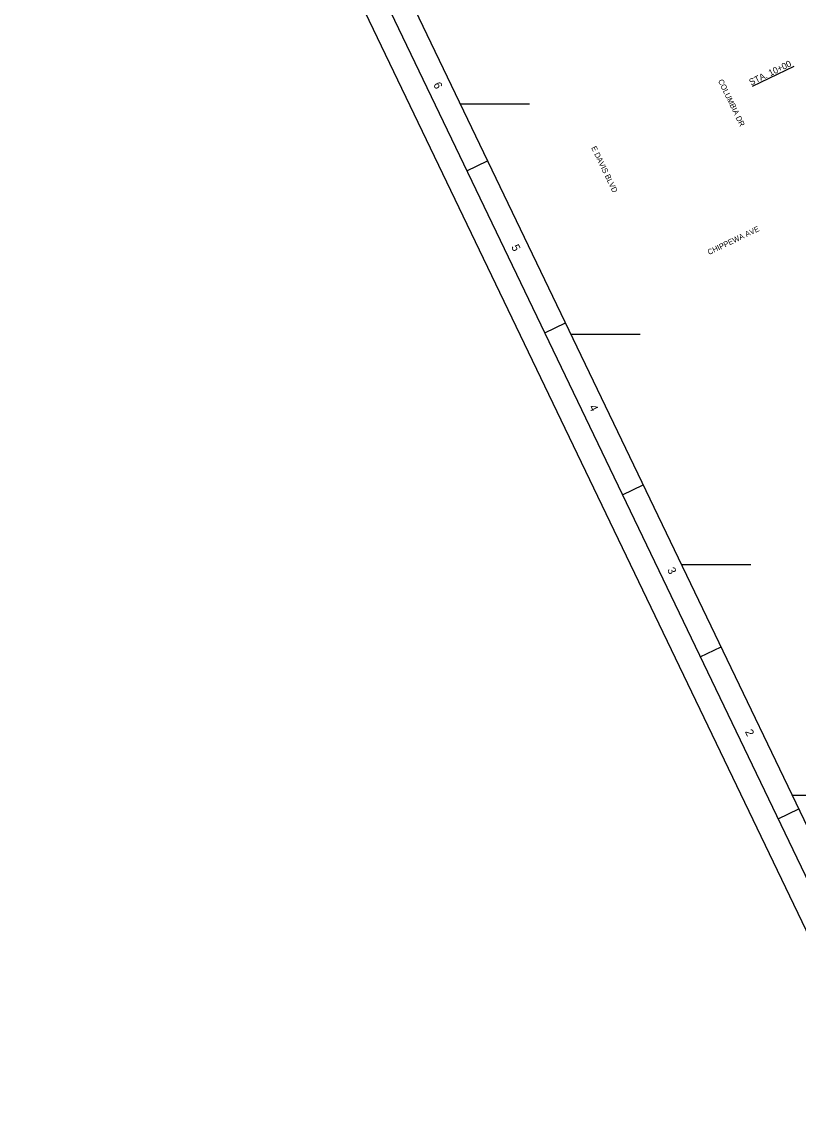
# Model space of a CAD drawing. Extents: x 508947 to 513916, y 1303283 to 1308721.
# Drawn here: x 508947 to 510632, y 1303283 to 1305678 of the extents above; entities that cross this region are included whole.
import ezdxf

# ---------------------------------------------------------------- set-up
doc = ezdxf.new("R2010")
doc.units = 0
for name, color, linetype in [('G-ANNO-NPLT', 7, 'Continuous'), ('G-ANNO-TTLB', 7, 'Continuous'), ('V-ALGN-TEXT', 7, 'Continuous'), ('V-ROAD-IDEN', 7, 'Continuous'), ('V-TOPO-COOR-STAT', 7, 'Continuous')]:
    doc.layers.add(name, color=color, linetype=linetype)

msp = doc.modelspace()

# ---------------------------------------------------------------- linework, layer by layer
at = {"layer": 'G-ANNO-NPLT'}
msp.add_lwpolyline([(512011.7, 1308720.8), (513916.1, 1304754.3), (510851.1, 1303282.7), (508946.7, 1307249.2)], close=True, dxfattribs=at)
at = {"layer": 'G-ANNO-TTLB'}
for p, q in [((509911.5, 1305355.2), (509956.6, 1305376.9)), ((510080.3, 1305003.7), (510125.4, 1305025.3)), ((510249.1, 1304652.1), (510294.2, 1304673.7)), ((510417.9, 1304300.5), (510463, 1304322.2)), ((510586.7, 1303948.9), (510631.8, 1303970.6))]:
    msp.add_line(p, q, dxfattribs=at)
for points in [[(509013.4, 1307225.8), (510874.5, 1303349.5), (513849.4, 1304777.8), (511988.3, 1308654.1)], [(513782.7, 1304801.2), (511997.3, 1308519.8), (509112.6, 1307134.8), (510898, 1303416.2)]]:
    msp.add_lwpolyline(points, close=True, dxfattribs=at)
at = {"layer": 'V-ALGN-TEXT'}
msp.add_line((510620.6, 1305581.6), (510530.5, 1305538.3), dxfattribs=at)
at = {"layer": 'V-TOPO-COOR-STAT'}
for p, q in [((510047.2, 1305500), (509897.5, 1305500)), ((510287.3, 1305000), (510137.5, 1305000)), ((510527.3, 1304500), (510377.6, 1304500)), ((510767.4, 1304000), (510617.6, 1304000))]:
    msp.add_line(p, q, dxfattribs=at)

# ---------------------------------------------------------------- texts
at = {"layer": 'G-ANNO-TTLB'}
for s, p in [('6', (509838.2, 1305542.6)), ('5', (510007.3, 1305190.3)), ('4', (510176, 1304842.9)), ('3', (510345.5, 1304489.7)), ('2', (510514.3, 1304138.3))]:
    msp.add_text(s, height=17.5, rotation=295.6468, dxfattribs=at).set_placement(p)
at = {"layer": 'V-ALGN-TEXT'}
msp.add_text('STA. 10+00', height=13.92, rotation=25.6468, dxfattribs=at).set_placement((510527.8, 1305540.1))
at = {"layer": 'V-ROAD-IDEN'}
for s, rotation, p in [('COLUMBIA DR', 295.6468, (510456, 1305550.2)), ('E DAVIS BLVD', 295.6468, (510180.9, 1305405.2)), ('CHIPPEWA AVE', 25.6468, (510437.1, 1305172.2))]:
    msp.add_text(s, height=12, rotation=rotation, dxfattribs=at).set_placement(p)

doc.saveas('drawing.dxf')
